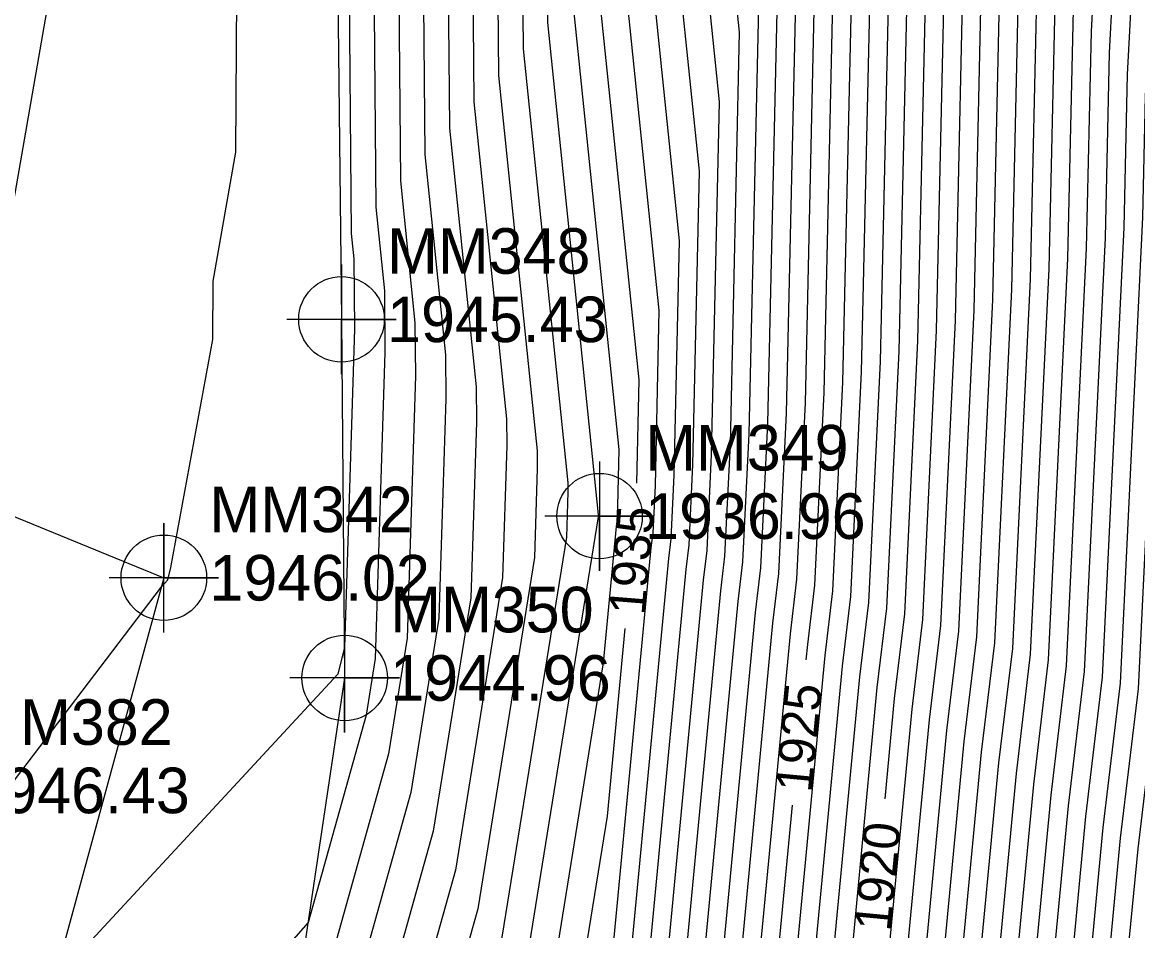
# Model space of a CAD drawing. Extents: x 1004378 to 1005103, y 553854 to 554288.
# Drawn here: x 1004929.3 to 1004990.4, y 553981 to 554030.8 of the extents above; entities that cross this region are included whole.
import ezdxf

# ---------------------------------------------------------------- set-up
doc = ezdxf.new("R2010")
doc.units = 0
for name, color, linetype in [('DTM Contours Major', 7, 'Continuous'), ('DTM Contours Major Text', 7, 'Continuous'), ('DTM Contours Minor', 7, 'Continuous'), ('Exist DTM Breakline', 7, 'Continuous'), ('Exist DTM Breakline Cogo Elevation', 7, 'Continuous'), ('Exist DTM Breakline Cogo Number', 7, 'Continuous'), ('Exist DTM Breakline Cogo Point CELL', 7, 'Continuous'), ('Exist DTM Regular Point CELL', 7, 'Continuous'), ('Exist DTM Regular Point Cogo Elevation', 7, 'Continuous'), ('Exist DTM Regular Point Cogo Number', 7, 'Continuous'), ('Exist Roads Soil', 7, 'Continuous'), ('Exist Roads Soil Cogo Elevation', 7, 'Continuous'), ('Exist Roads Soil Cogo Number', 7, 'Continuous'), ('Exist Roads Soil Cogo Point CELL', 7, 'Continuous')]:
    doc.layers.add(name, color=color, linetype=linetype)

msp = doc.modelspace()

# ---------------------------------------------------------------- linework, layer by layer
at = {"layer": 'DTM Contours Major'}
for points in [[(1004962.871, 554103.868), (1004961.056, 554099.139), (1004960.026, 554093.701), (1004959.475, 554092.482), (1004958.495, 554086.221), (1004956.453, 554076.695), (1004957.899, 554064.565), (1004959.313, 554057.782), (1004961.493, 554050.599), (1004960.632, 554047.97), (1004960.758, 554033.678), (1004963.076, 554011.188), (1004962.949, 554005.526)], [(1004970.528, 554093.236), (1004969.641, 554088.552), (1004969.416, 554088.055), (1004967.45, 554075.492), (1004969.542, 554073.85), (1004972.596, 554066.826), (1004972.547, 554060.122), (1004971.354, 554054.113), (1004973.706, 554047.918), (1004974.042, 554047.122), (1004974.026, 554046.818), (1004973.213, 554010.493), (1004972.706, 553999.94), (1004972.315, 553996.671), (1004972.236, 553995.839)], [(1004974.172, 554084.471), (1004973.846, 554082.386), (1004977.708, 554079.356), (1004979.951, 554076.865), (1004980.929, 554074.931), (1004981.177, 554073.474), (1004981.105, 554072.871), (1004980.838, 554060.621), (1004980.413, 554056.78), (1004977.827, 554047.365), (1004979.146, 554044.236), (1004978.97, 554040.918), (1004978.353, 554013.324), (1004977.634, 553998.359), (1004977.079, 553993.724), (1004976.557, 553988.222)], [(1004952.659, 554065.091), (1004953.349, 554059.3), (1004954.06, 554055.889), (1004955.156, 554052.277), (1004953.842, 554048.264), (1004954.035, 554026.446), (1004955.827, 554009.057), (1004955.839, 554007.597), (1004955.608, 554000.346), (1004953.019, 553984.313), (1004948.054, 553966.564)], [(1004966.938, 554051.86), (1004967.829, 554048.921), (1004967.422, 554047.677), (1004967.482, 554040.91), (1004968.579, 554030.261), (1004968.073, 554007.661), (1004967.778, 554001.521), (1004967.551, 553999.619), (1004964.757, 553970.225), (1004964.471, 553967.778), (1004960.654, 553952.767)], [(1004990.518, 554049.324), (1004989.746, 554042.345), (1004988.945, 554039.431), (1004989.353, 554038.463), (1004988.859, 554029.118), (1004988.632, 554018.987), (1004987.49, 553995.198), (1004986.608, 553987.828), (1004985.684, 553978.101), (1004983.38, 553958.418), (1004981.497, 553951.011), (1004981.379, 553950.073)], [(1004947.118, 554041.088), (1004947.311, 554019.215), (1004947.454, 554017.827), (1004947.487, 554013.967), (1004946.931, 553996.538), (1004946.571, 553995.053), (1004931.009, 553978.241), (1004928.196, 553974.545), (1004916.189, 553970.124), (1004914.888, 553969.412), (1004912.358, 553969.149), (1004911.765, 553968.617), (1004911.067, 553969.318), (1004903.448, 553970.699)], [(1004984.132, 554039.131), (1004983.915, 554035.018), (1004983.493, 554016.156), (1004982.562, 553996.779), (1004981.844, 553990.776), (1004980.452, 553976.132), (1004978.652, 553960.758), (1004976.062, 553950.567), (1004975.294, 553944.427), (1004974.577, 553939.804)], [(1004962.31, 553997.555), (1004961.333, 553987.27), (1004959.141, 553973.696), (1004957.624, 553968.273), (1004957.585, 553968.134), (1004953.163, 553954.39), (1004946.098, 553947.597), (1004944.639, 553946.764), (1004920.141, 553940.962), (1004919.187, 553940.926), (1004918.652, 553940.867), (1004916.351, 553941.407), (1004903.524, 553943.188), (1004903.229, 553940.965)], [(1004971.479, 553987.875), (1004969.989, 553972.194), (1004969.198, 553965.438), (1004965.192, 553949.68), (1004964.904, 553947.376), (1004960.748, 553920.578), (1004960.368, 553920.099), (1004959.949, 553919.572), (1004959.874, 553919.536), (1004954.889, 553917.367), (1004952.025, 553915.484), (1004933.597, 553906.315), (1004932.685, 553906.503)]]:
    msp.add_lwpolyline(points, dxfattribs=at)
at = {"layer": 'DTM Contours Minor'}
for points in [[(1004892.909, 553980.228), (1004909.736, 553977.519), (1004919.988, 553982.517), (1004925.173, 553984.426), (1004936.898, 553999.835), (1004937.254, 554000.219), (1004937.418, 554000.896), (1004939.715, 554013.407), (1004939.746, 554016.607), (1004940.982, 554023.681), (1004941.12, 554046.622), (1004942.146, 554051.575), (1004941.271, 554057.545), (1004943.194, 554079.367), (1004940.844, 554083.886), (1004927.509, 554103.798), (1004927.675, 554104.761), (1004926.297, 554106.983), (1004913.409, 554117.504), (1004910.609, 554119.787), (1004911.321, 554123.435)], [(1004896.871, 553987.94), (1004907.319, 553986.258), (1004918.577, 553991.746), (1004920.602, 553996.072), (1004926.171, 554004.786), (1004927.401, 554011.483), (1004927.417, 554013.109), (1004930.834, 554032.674), (1004930.895, 554042.816), (1004933.912, 554057.37), (1004933.33, 554061.338), (1004934.608, 554075.845), (1004923.665, 554096.889), (1004921.296, 554100.426), (1004922.463, 554107.183), (1004921.461, 554108.798), (1004912.095, 554116.444), (1004910.06, 554118.103), (1004910.577, 554120.754)], [(1004948.41, 554048.498), (1004948.656, 554020.661), (1004949.129, 554016.073), (1004949.157, 554012.693), (1004948.622, 553995.909), (1004948.121, 553992.807), (1004944.939, 553981.431), (1004934.117, 553969.131), (1004932.752, 553967.238), (1004929.819, 553965.57), (1004924.739, 553964.771), (1004916.73, 553963.94), (1004913.587, 553961.121), (1004911.131, 553960.847), (1004910.199, 553961.066), (1004909.391, 553960.658), (1004907.185, 553961.606), (1004903.082, 553965.731), (1004892.29, 553967.686), (1004891.326, 553967.931), (1004890.511, 553967.035)], [(1004949.768, 554048.44), (1004950.001, 554022.107), (1004950.803, 554014.319), (1004950.827, 554011.419), (1004950.368, 553997.019), (1004949.345, 553990.683), (1004942.849, 553967.456), (1004941.373, 553965.778), (1004941.187, 553965.52), (1004932.749, 553960.721), (1004926.659, 553959.763), (1004919.896, 553959.51), (1004911.966, 553958.627), (1004908.059, 553959.544), (1004904.674, 553957.836), (1004895.429, 553961.81), (1004895.097, 553962.143), (1004894.225, 553962.301), (1004892.484, 553962.744), (1004891.01, 553961.125)], [(1004951.126, 554048.381), (1004951.345, 554023.554), (1004952.478, 554012.565), (1004952.498, 554010.145), (1004952.115, 553998.128), (1004950.57, 553988.56), (1004944.141, 553965.574), (1004943.976, 553964.983), (1004943.524, 553963.577), (1004942.801, 553962.882), (1004934.598, 553958.198), (1004932.304, 553957.655), (1004919.808, 553957.187), (1004912.802, 553956.407), (1004905.92, 553958.023), (1004899.957, 553955.013), (1004894.62, 553957.307), (1004893.641, 553957.556), (1004891.509, 553955.214)], [(1004952.484, 554048.322), (1004952.69, 554025), (1004954.152, 554010.811), (1004954.168, 554008.871), (1004953.861, 553999.237), (1004951.794, 553986.437), (1004946.067, 553965.959), (1004945.92, 553965.433), (1004944.901, 553962.265), (1004943.272, 553960.699), (1004936.032, 553956.565), (1004930.566, 553955.27), (1004919.719, 553954.864), (1004913.638, 553954.187), (1004903.78, 553956.501), (1004895.24, 553952.191), (1004894.867, 553952.351), (1004894.798, 553952.369), (1004892.008, 553949.303)], [(1004955.2, 554048.205), (1004955.379, 554027.893), (1004957.501, 554007.303), (1004957.509, 554006.323), (1004957.354, 554001.455), (1004954.243, 553982.19), (1004949.919, 553966.731), (1004949.808, 553966.333), (1004947.655, 553959.64), (1004944.214, 553956.331), (1004938.901, 553953.298), (1004927.091, 553950.501), (1004919.542, 553950.218), (1004915.309, 553949.747), (1004899.502, 553953.458), (1004898.18, 553952.79), (1004897.542, 553947.998), (1004894.519, 553939.143), (1004893.007, 553937.482)], [(1004956.558, 554048.146), (1004956.724, 554029.339), (1004959.176, 554005.549), (1004959.18, 554005.049), (1004959.101, 554002.565), (1004955.467, 553980.066), (1004951.846, 553967.116), (1004951.753, 553966.783), (1004949.032, 553958.328), (1004944.685, 553954.148), (1004940.335, 553951.664), (1004925.354, 553948.116), (1004919.453, 553947.895), (1004916.145, 553947.527), (1004901.925, 553950.865), (1004899.622, 553951.185), (1004898.923, 553945.93), (1004894.328, 553932.475), (1004893.506, 553931.571)], [(1004957.916, 554048.088), (1004958.069, 554030.785), (1004960.85, 554003.795), (1004960.85, 554003.775), (1004960.847, 554003.674), (1004956.692, 553977.943), (1004953.772, 553967.502), (1004953.697, 553967.233), (1004950.409, 553957.015), (1004945.156, 553951.964), (1004941.77, 553950.031), (1004923.616, 553945.732), (1004919.364, 553945.572), (1004916.98, 553945.307), (1004906.734, 553947.712), (1004900.923, 553948.519), (1004900.303, 553943.862), (1004894.138, 553925.806), (1004894.005, 553925.66)], [(1004972.981, 554045.52), (1004972.185, 554009.926), (1004971.721, 554000.256), (1004971.362, 553997.261), (1004968.942, 553971.8), (1004968.253, 553965.906), (1004964.105, 553949.591), (1004963.865, 553947.671), (1004960.401, 553925.336), (1004957.491, 553921.673), (1004957.35, 553921.495), (1004957.063, 553921.358), (1004955.215, 553920.554), (1004954.153, 553919.855), (1004932.16, 553908.913), (1004916.353, 553912.182), (1004913.842, 553914.186), (1004913.087, 553911.609), (1004912.621, 553908.909), (1004907.637, 553886.746), (1004907.279, 553884.335), (1004906.612, 553883.292), (1004908.282, 553879.28)], [(1004975.015, 554045.638), (1004974.241, 554011.059), (1004973.692, 553999.624), (1004973.268, 553996.082), (1004971.035, 553972.588), (1004970.143, 553964.97), (1004966.279, 553949.768), (1004965.943, 553947.081), (1004961.807, 553920.414), (1004961.699, 553919.562), (1004961.557, 553918.68), (1004961.124, 553917.06), (1004960.01, 553916.55), (1004954.564, 553914.18), (1004949.897, 553911.112), (1004935.034, 553903.717), (1004920.298, 553906.764), (1004913.738, 553897.346), (1004910.842, 553884.469), (1004910.705, 553883.545), (1004910.449, 553883.146), (1004912.725, 553877.68)], [(1004976.003, 554044.458), (1004975.269, 554011.625), (1004974.678, 553999.308), (1004974.221, 553995.492), (1004972.081, 553972.981), (1004971.089, 553964.502), (1004967.366, 553949.857), (1004966.982, 553946.786), (1004962.993, 553921.064), (1004962.757, 553919.209), (1004962.62, 553918.356), (1004961.517, 553914.225), (1004958.675, 553912.924), (1004954.239, 553910.994), (1004947.768, 553906.74), (1004936.47, 553901.118), (1004925.269, 553903.435), (1004913.007, 553885.833), (1004912.444, 553883.33), (1004912.418, 553883.151), (1004912.368, 553883.073), (1004914.946, 553876.88)], [(1004976.992, 554043.278), (1004976.297, 554012.192), (1004975.663, 553998.992), (1004975.174, 553994.903), (1004973.128, 553973.375), (1004972.034, 553964.034), (1004968.453, 553949.946), (1004968.021, 553946.491), (1004964.178, 553921.714), (1004963.816, 553918.856), (1004963.683, 553918.032), (1004961.91, 553911.39), (1004957.339, 553909.298), (1004953.913, 553907.807), (1004945.64, 553902.368), (1004937.907, 553898.52), (1004930.24, 553900.106), (1004920.136, 553885.602), (1004914.696, 553882.016), (1004917.167, 553876.081)], [(1004971.881, 554041.705), (1004971.157, 554009.36), (1004970.735, 554000.573), (1004970.409, 553997.85), (1004967.896, 553971.406), (1004967.307, 553966.374), (1004963.018, 553949.502), (1004962.826, 553947.966), (1004960.054, 553930.094), (1004956.322, 553925.395), (1004955.382, 553924.012), (1004954.895, 553923.733), (1004952.275, 553922.234), (1004930.724, 553911.511), (1004918.442, 553914.051), (1004912.975, 553918.414), (1004911.33, 553912.804), (1004910.317, 553906.926), (1004906.034, 553887.884), (1004905.566, 553884.73), (1004904.694, 553883.365), (1004906.061, 553880.08)], [(1004977.981, 554042.098), (1004977.325, 554012.758), (1004976.649, 553998.676), (1004976.126, 553994.313), (1004974.174, 553973.769), (1004972.98, 553963.566), (1004969.54, 553950.035), (1004969.06, 553946.196), (1004965.364, 553922.363), (1004964.874, 553918.503), (1004964.745, 553917.708), (1004962.303, 553908.555), (1004956.004, 553905.672), (1004953.588, 553904.62), (1004943.512, 553897.997), (1004939.343, 553895.922), (1004935.21, 553896.777), (1004929.764, 553888.959), (1004917.155, 553880.646), (1004919.388, 553875.281)], [(1004979.959, 554039.738), (1004979.381, 554013.891), (1004978.62, 553998.043), (1004978.032, 553993.134), (1004976.267, 553974.557), (1004974.871, 553962.63), (1004971.714, 553950.212), (1004971.138, 553945.606), (1004967.735, 553923.663), (1004966.99, 553917.797), (1004966.871, 553917.06), (1004963.088, 553902.885), (1004953.334, 553898.42), (1004952.937, 553898.247), (1004949.019, 553895.671), (1004940.949, 553890.351), (1004922.072, 553877.905), (1004923.831, 553873.681)], [(1004966.137, 554039.463), (1004967.478, 554026.447), (1004967.045, 554007.095), (1004966.793, 554001.837), (1004966.598, 554000.209), (1004963.711, 553969.831), (1004963.525, 553968.246), (1004958.67, 553949.147), (1004958.67, 553949.145), (1004958.667, 553949.126), (1004958.663, 553949.121), (1004950.096, 553936.518), (1004949.909, 553936.411), (1004929.348, 553924.643), (1004924.856, 553923.056), (1004913.836, 553931.817), (1004908.728, 553932.526), (1004908.586, 553931.455), (1004907.061, 553926.988), (1004904.303, 553917.582), (1004901.098, 553898.992)], [(1004980.948, 554038.558), (1004980.409, 554014.457), (1004979.606, 553997.727), (1004978.985, 553992.545), (1004977.313, 553974.951), (1004975.816, 553962.162), (1004972.801, 553950.301), (1004972.177, 553945.311), (1004968.92, 553924.312), (1004968.048, 553917.444), (1004967.934, 553916.736), (1004963.481, 553900.05), (1004955.023, 553896.178), (1004951.726, 553894.465), (1004940.859, 553887.301), (1004924.53, 553876.535), (1004926.052, 553872.881)], [(1004988.333, 554039.04), (1004987.87, 554030.298), (1004987.604, 554018.421), (1004986.505, 553995.514), (1004985.655, 553988.418), (1004984.637, 553977.708), (1004982.434, 553958.886), (1004980.41, 553950.922), (1004979.45, 553943.247), (1004977.219, 553928.86), (1004975.456, 553914.973), (1004975.374, 553914.469), (1004970.438, 553895.973), (1004969.024, 553890.84), (1004965.116, 553879.433), (1004942.966, 553867.387), (1004942.363, 553867.059)], [(1004964.792, 554038.017), (1004966.378, 554022.632), (1004966.017, 554006.528), (1004965.807, 554002.153), (1004965.645, 554000.798), (1004962.665, 553969.437), (1004962.58, 553968.714), (1004960.36, 553959.981), (1004957.294, 553950.453), (1004953.909, 553947.198), (1004948.774, 553939.645), (1004948.663, 553939.581), (1004936.373, 553932.547), (1004923.184, 553927.887), (1004915.385, 553934.086), (1004907.427, 553935.191), (1004907.205, 553933.523), (1004904.829, 553926.563), (1004902.546, 553918.777), (1004898.793, 553897.009)], [(1004970.78, 554037.89), (1004970.129, 554008.794), (1004969.75, 554000.889), (1004969.456, 553998.44), (1004966.85, 553971.012), (1004966.362, 553966.842), (1004961.931, 553949.413), (1004961.787, 553948.261), (1004959.707, 553934.852), (1004956.907, 553931.326), (1004954.06, 553927.139), (1004953.648, 553926.903), (1004944.652, 553921.754), (1004929.287, 553914.109), (1004920.531, 553915.92), (1004912.107, 553922.642), (1004909.573, 553913.998), (1004908.012, 553904.943), (1004904.431, 553889.023), (1004903.852, 553885.125), (1004902.775, 553883.437), (1004903.84, 553880.88)], [(1004981.937, 554037.378), (1004981.437, 554015.023), (1004980.591, 553997.411), (1004979.938, 553991.955), (1004978.359, 553975.345), (1004976.762, 553961.694), (1004973.888, 553950.39), (1004973.216, 553945.017), (1004970.106, 553924.962), (1004969.106, 553917.091), (1004968.997, 553916.413), (1004963.874, 553897.215), (1004958.674, 553894.835), (1004949.941, 553890.297), (1004940.77, 553884.251), (1004926.989, 553875.165), (1004928.273, 553872.081)], [(1004990.374, 554037.886), (1004989.848, 554027.938), (1004989.66, 554019.554), (1004988.476, 553994.882), (1004987.561, 553987.239), (1004986.73, 553978.495), (1004984.325, 553957.95), (1004982.584, 553951.1), (1004981.528, 553942.657), (1004979.589, 553930.159), (1004977.572, 553914.267), (1004977.5, 553913.821), (1004973.135, 553897.463), (1004971.078, 553890), (1004965.395, 553873.413), (1004952.028, 553866.143), (1004949.387, 553864.706)], [(1004991.395, 554037.308), (1004990.837, 554026.758), (1004990.688, 554020.12), (1004989.461, 553994.565), (1004988.514, 553986.649), (1004987.776, 553978.889), (1004985.27, 553957.481), (1004983.671, 553951.188), (1004982.567, 553942.362), (1004980.775, 553930.808), (1004978.63, 553913.914), (1004978.563, 553913.497), (1004974.483, 553898.208), (1004972.105, 553889.579), (1004965.535, 553870.402), (1004956.559, 553865.52), (1004952.898, 553863.53)], [(1004992.416, 554036.731), (1004991.826, 554025.578), (1004991.716, 554020.686), (1004990.447, 553994.249), (1004989.467, 553986.06), (1004988.823, 553979.283), (1004986.216, 553957.013), (1004984.758, 553951.277), (1004983.606, 553942.067), (1004981.96, 553931.458), (1004979.688, 553913.561), (1004979.626, 553913.173), (1004975.831, 553898.953), (1004973.133, 553889.159), (1004965.675, 553867.392), (1004961.09, 553864.898), (1004956.41, 553862.353)], [(1004963.448, 554036.571), (1004965.277, 554018.817), (1004964.989, 554005.962), (1004964.822, 554002.47), (1004964.692, 554001.388), (1004961.753, 553970.463), (1004961.589, 553969.449), (1004961.476, 553969.044), (1004961.473, 553969.034), (1004955.917, 553951.766), (1004949.132, 553945.241), (1004947.453, 553942.771), (1004947.416, 553942.75), (1004943.398, 553940.451), (1004921.511, 553932.717), (1004916.934, 553936.356), (1004906.126, 553937.857), (1004905.825, 553935.591), (1004902.597, 553926.138), (1004900.789, 553919.972), (1004896.488, 553895.026)], [(1004982.926, 554036.198), (1004982.465, 554015.589), (1004981.577, 553997.095), (1004980.891, 553991.365), (1004979.406, 553975.738), (1004977.707, 553961.226), (1004974.975, 553950.478), (1004974.255, 553944.722), (1004971.291, 553925.611), (1004970.165, 553916.738), (1004970.06, 553916.089), (1004964.266, 553894.38), (1004962.325, 553893.491), (1004948.155, 553886.129), (1004940.68, 553881.201), (1004929.448, 553873.795), (1004930.494, 553871.281)], [(1004993.436, 554036.154), (1004992.815, 554024.398), (1004992.744, 554021.253), (1004991.433, 553993.933), (1004990.419, 553985.47), (1004989.869, 553979.677), (1004987.161, 553956.545), (1004985.845, 553951.366), (1004984.645, 553941.773), (1004983.146, 553932.108), (1004980.746, 553913.208), (1004980.689, 553912.849), (1004977.179, 553899.699), (1004974.16, 553888.739), (1004965.815, 553864.382), (1004965.62, 553864.276), (1004959.921, 553861.177)], [(1004962.103, 554035.124), (1004964.176, 554015.003), (1004963.961, 554005.396), (1004963.836, 554002.786), (1004963.739, 554001.977), (1004961.543, 553978.867), (1004960.365, 553971.573), (1004959.55, 553968.659), (1004959.529, 553968.584), (1004954.54, 553953.078), (1004946.569, 553945.413), (1004946.073, 553945.13), (1004931.594, 553941.701), (1004919.839, 553937.548), (1004918.483, 553938.626), (1004904.825, 553940.523), (1004904.444, 553937.659), (1004900.366, 553925.713), (1004899.032, 553921.166), (1004895.735, 553902.041), (1004895.123, 553902.853)], [(1004969.679, 554034.076), (1004969.101, 554008.227), (1004968.764, 554001.205), (1004968.504, 553999.029), (1004965.804, 553970.618), (1004965.416, 553967.31), (1004960.844, 553949.324), (1004960.748, 553948.556), (1004959.36, 553939.61), (1004957.492, 553937.258), (1004952.739, 553930.265), (1004952.402, 553930.072), (1004937.029, 553921.274), (1004927.851, 553916.707), (1004922.62, 553917.789), (1004911.24, 553926.87), (1004907.816, 553915.193), (1004905.707, 553902.959), (1004902.829, 553890.161), (1004902.139, 553885.52), (1004900.857, 553883.51), (1004901.619, 553881.68)], [(1004984.903, 554033.838), (1004984.52, 554016.722), (1004983.548, 553996.462), (1004982.797, 553990.186), (1004981.498, 553976.526), (1004979.598, 553960.29), (1004977.149, 553950.656), (1004976.333, 553944.132), (1004973.662, 553926.911), (1004972.281, 553916.032), (1004972.186, 553915.441), (1004966.394, 553893.738), (1004965.943, 553892.101), (1004964.697, 553888.464), (1004955.582, 553883.507), (1004944.585, 553877.793), (1004940.501, 553875.1), (1004934.365, 553871.055), (1004934.936, 553869.681)], [(1004985.892, 554032.658), (1004985.548, 554017.288), (1004984.533, 553996.146), (1004983.749, 553989.597), (1004982.545, 553976.92), (1004980.543, 553959.822), (1004978.236, 553950.745), (1004977.372, 553943.837), (1004974.848, 553927.56), (1004973.339, 553915.679), (1004973.248, 553915.117), (1004967.742, 553894.483), (1004966.97, 553891.681), (1004964.836, 553885.454), (1004949.23, 553876.966), (1004942.8, 553873.625), (1004940.412, 553872.05), (1004936.823, 553869.685), (1004937.157, 553868.881)], [(1004959.413, 554032.232), (1004961.975, 554007.374), (1004961.905, 554004.263), (1004961.865, 554003.418), (1004961.833, 554003.156), (1004961.122, 553995.674), (1004957.916, 553975.82), (1004955.698, 553967.888), (1004955.641, 553967.684), (1004951.786, 553955.703), (1004945.627, 553949.78), (1004943.204, 553948.397), (1004921.879, 553943.347), (1004919.275, 553943.249), (1004917.816, 553943.087), (1004911.542, 553944.56), (1004902.224, 553945.854), (1004901.684, 553941.794), (1004895.902, 553924.863), (1004895.519, 553923.556), (1004894.571, 553918.057), (1004894.395, 553918.29)], [(1004986.881, 554031.478), (1004986.576, 554017.855), (1004985.519, 553995.83), (1004984.702, 553989.007), (1004983.591, 553977.314), (1004981.489, 553959.354), (1004979.323, 553950.833), (1004978.411, 553943.542), (1004976.033, 553928.21), (1004974.397, 553915.326), (1004974.311, 553914.793), (1004969.09, 553895.228), (1004967.997, 553891.26), (1004964.976, 553882.444), (1004942.879, 553870.426), (1004941.014, 553869.457), (1004940.322, 553869), (1004939.282, 553868.314), (1004939.379, 553868.082)]]:
    msp.add_lwpolyline(points, dxfattribs=at)
at = {"layer": 'Exist DTM Breakline'}
msp.add_lwpolyline([(1004908.599, 554113.626), (1004928.542, 554104.358), (1004950.697, 554094.299), (1004945.541, 554080.331), (1004948.745, 554053.974), (1004946.395, 554048.586), (1004946.774, 554014.511), (1004946.946, 553994.845), (1004942.426, 553964.624), (1004933.56, 553959.38), (1004919.92, 553960.138), (1004910.869, 553961.543), (1004894.885, 553951.978), (1004894.101, 553924.52), (1004896.848, 553886.739), (1004896.026, 553883.694)], dxfattribs=at)
at = {"layer": 'Exist DTM Breakline Cogo Point CELL'}
for points in [[(1004946.774, 554017.511), (1004946.774, 554011.511), (1004946.774, 554014.511), (1004949.774, 554014.511), (1004943.774, 554014.511)], [(1004946.946, 553997.845), (1004946.946, 553991.845), (1004946.946, 553994.845), (1004949.946, 553994.845), (1004943.946, 553994.845)]]:
    msp.add_lwpolyline(points, dxfattribs=at)
for centre in [(1004946.774, 554014.511), (1004946.946, 553994.845)]:
    msp.add_circle(centre, 2.344, dxfattribs=at)
at = {"layer": 'Exist DTM Regular Point CELL'}
msp.add_lwpolyline([(1004960.921, 554006.721), (1004960.921, 554000.721), (1004960.921, 554003.721), (1004963.921, 554003.721), (1004957.921, 554003.721)], dxfattribs=at)
msp.add_circle((1004960.921, 554003.721), 2.344, dxfattribs=at)
at = {"layer": 'Exist Roads Soil'}
msp.add_lwpolyline([(1004902.345, 554049.201), (1004911.013, 554044.44), (1004908.227, 554025.602), (1004914.669, 554009.493), (1004937.036, 554000.34), (1004928.257, 553968.154), (1004911.901, 553969.693), (1004894.395, 553961.828)], dxfattribs=at)
at = {"layer": 'Exist Roads Soil Cogo Point CELL'}
msp.add_lwpolyline([(1004937.036, 553997.34), (1004937.036, 554003.34), (1004937.036, 554000.34), (1004940.036, 554000.34), (1004934.036, 554000.34)], dxfattribs=at)
msp.add_circle((1004937.036, 554000.34), 2.344, dxfattribs=at)

# ---------------------------------------------------------------- texts
at = {"layer": 'DTM Contours Major Text'}
for s, rotation, p in [('1935', 85.41769, (1004963.428, 553998.247)), ('1925', 84.57123, (1004972.545, 553988.525)), ('1920', 84.57123, (1004976.866, 553980.908))]:
    msp.add_text(s, height=2, rotation=rotation, dxfattribs=at).set_placement(p)
at = {"layer": 'Exist DTM Breakline Cogo Elevation'}
for s, p in [('1945.43', (1004949.274, 554013.261)), ('1944.96', (1004949.446, 553993.595))]:
    msp.add_text(s, height=2.5, dxfattribs=at).set_placement(p)
at = {"layer": 'Exist DTM Breakline Cogo Number'}
for s, p in [('MM348', (1004949.274, 554017.011)), ('MM350', (1004949.446, 553997.345))]:
    msp.add_text(s, height=2.5, dxfattribs=at).set_placement(p)
at = {"layer": 'Exist DTM Regular Point Cogo Elevation'}
for s, p in [('1936.96', (1004963.421, 554002.471)), ('1946.43', (1004926.372, 553987.427))]:
    msp.add_text(s, height=2.5, dxfattribs=at).set_placement(p)
at = {"layer": 'Exist DTM Regular Point Cogo Number'}
for s, p in [('MM349', (1004963.421, 554006.221)), ('MM382', (1004926.372, 553991.177))]:
    msp.add_text(s, height=2.5, dxfattribs=at).set_placement(p)
at = {"layer": 'Exist Roads Soil Cogo Elevation'}
msp.add_text('1946.02', height=2.5, dxfattribs=at).set_placement((1004939.536, 553999.09))
at = {"layer": 'Exist Roads Soil Cogo Number'}
msp.add_text('MM342', height=2.5, dxfattribs=at).set_placement((1004939.536, 554002.84))

doc.saveas('drawing.dxf')
